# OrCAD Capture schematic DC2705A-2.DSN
size B
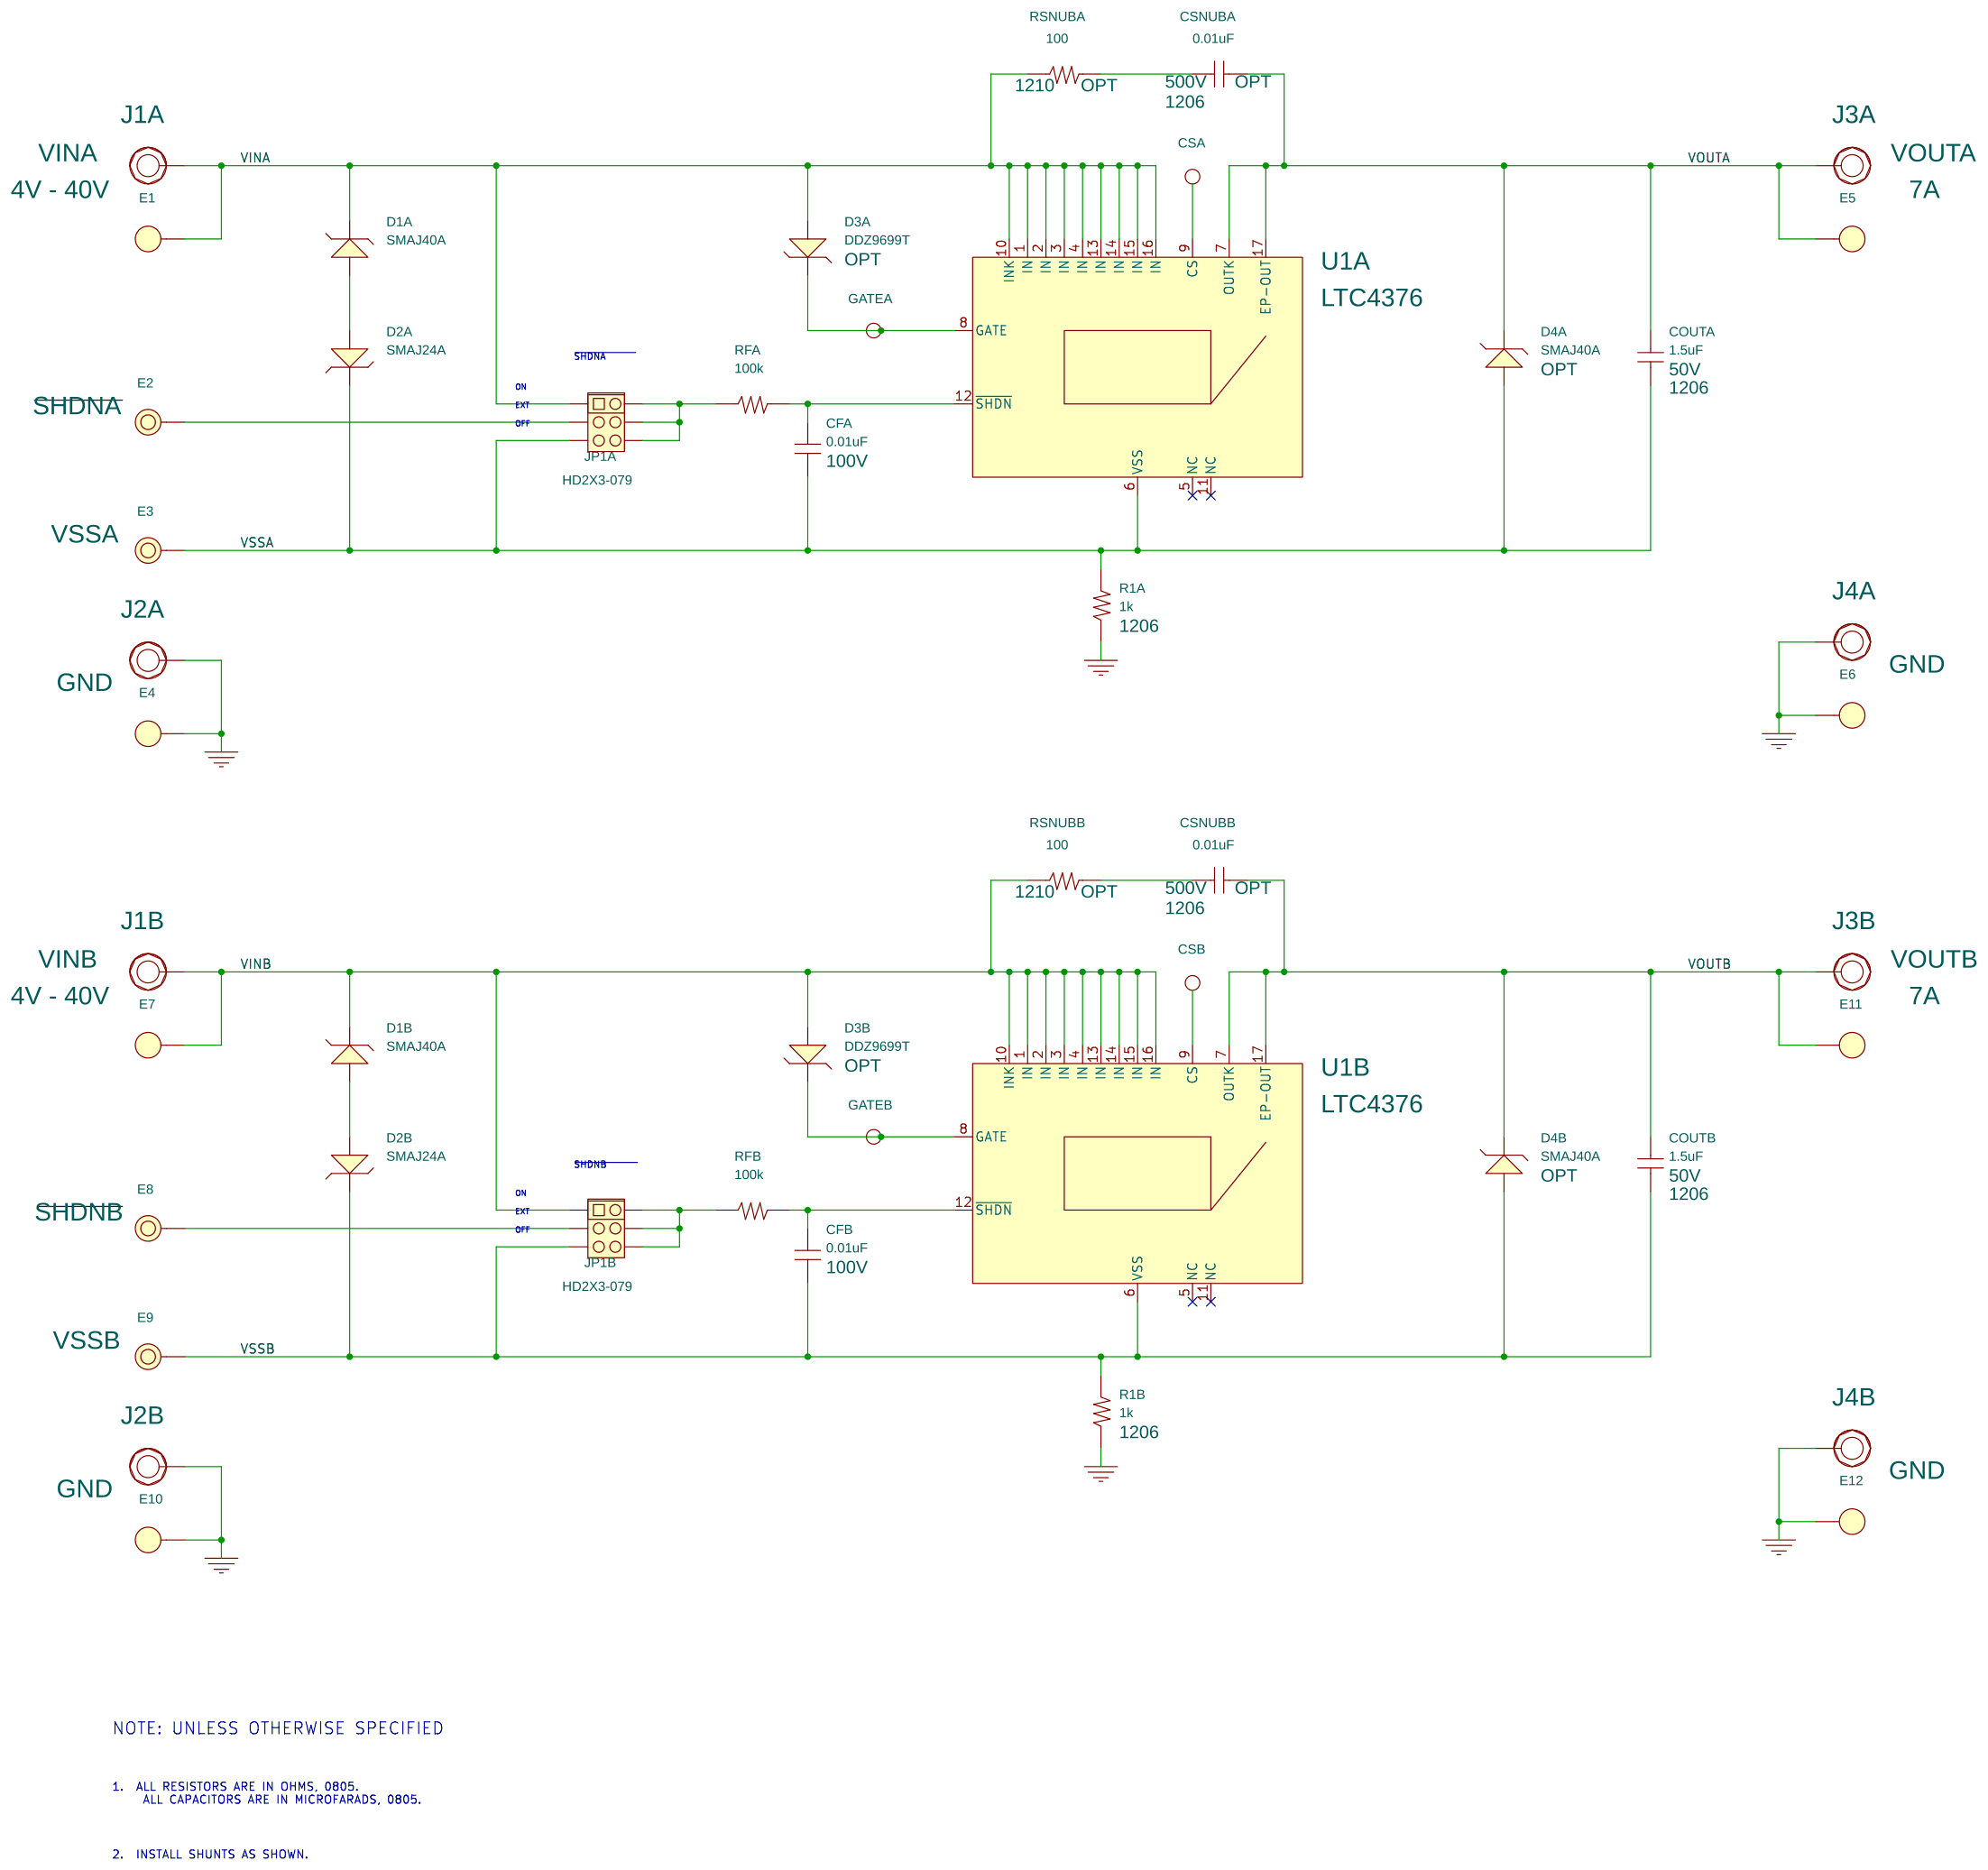
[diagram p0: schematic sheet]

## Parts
CFA  0.01uF  [0805]
CFB  0.01uF  [0805]
COUTA  1.5uF  [1206]
COUTB  1.5uF  [1206]
CSA  PAD100SMT  [PAD100SMT]
CSB  PAD100SMT  [PAD100SMT]
CSNUBA  0.01uF  [1206]
CSNUBB  0.01uF  [1206]
D1A  SMAJ40A  [SMA-DIODE]
D1B  SMAJ40A  [SMA-DIODE]
D2A  SMAJ24A  [SMA-DIODE]
D2B  SMAJ24A  [SMA-DIODE]
D3A  DDZ9699T  [SOD523]
D3B  DDZ9699T  [SOD523]
D4A  SMAJ40A  [SMA-DIODE]
D4B  SMAJ40A  [SMA-DIODE]
E1  MIL-MAX-2501  [MILL-MAX-2501]
E2  MIL-MAX-2308  [MILL-MAX-2308]
E3  MIL-MAX-2308  [MILL-MAX-2308]
E4  MIL-MAX-2501  [MILL-MAX-2501]
E5  MIL-MAX-2501  [MILL-MAX-2501]
E6  MIL-MAX-2501  [MILL-MAX-2501]
E7  MIL-MAX-2501  [MILL-MAX-2501]
E8  MIL-MAX-2308  [MILL-MAX-2308]
E9  MIL-MAX-2308  [MILL-MAX-2308]
E10  MIL-MAX-2501  [MILL-MAX-2501]
E11  MIL-MAX-2501  [MILL-MAX-2501]
E12  MIL-MAX-2501  [MILL-MAX-2501]
GATEA  PAD100SMT  [PAD100SMT]
GATEB  PAD100SMT  [PAD100SMT]
J1A  Banana Jack  [KEY-575]
J1B  Banana Jack  [KEY-575]
J2A  Banana Jack  [KEY-575]
J2B  Banana Jack  [KEY-575]
J3A  Banana Jack  [KEY-575]
J3B  Banana Jack  [KEY-575]
J4A  Banana Jack  [KEY-575]
J4B  Banana Jack  [KEY-575]
JP1A  HD2X3-079  [HD2X3-079]
JP1B  HD2X3-079  [HD2X3-079]
R1A  1k  [1206]
R1B  1k  [1206]
RFA  100k  [0805]
RFB  100k  [0805]
RSNUBA  100  [1210]
RSNUBB  100  [1210]
U1A  LTC4376  [DFN16DHD-5X4]
U1B  LTC4376  [DFN16DHD-5X4]

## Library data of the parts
CFA CFB = CAP-NP: VOLTAGE: 100V
COUTA COUTB = CAP-NP: VOLTAGE: 50V
CSA CSB GATEA GATEB = E-100-25
CSNUBA CSNUBB = CAP-NP: OPT: OPT; VOLTAGE: 500V
D1A D1B D2A D2B = SMAJ40A-SMA-DIODE
D3A D3B = DIODE-DDZ9699T-SOD523: OPT: OPT
D4A D4B = SMAJ40A-SMA-DIODE: OPT: OPT
E1 E4-E7 E10-E12 = E-094
E2 = E-064: 1ST PART FIELD: SHDNA
E3 = E-064: 1ST PART FIELD: VSSA
E8 = E-064: 1ST PART FIELD: SHDNB
E9 = E-064: 1ST PART FIELD: VSSB
J1A = E-KEY-575: 1ST PART FIELD: 4V - 40V; FUNTION: VINA
J1B = E-KEY-575: 1ST PART FIELD: 4V - 40V; FUNTION: VINB
J2A J2B J4A J4B = E-KEY-575: FUNTION: GND
J3A = E-KEY-575: 1ST PART FIELD: 7A; FUNTION: VOUTA
J3B = E-KEY-575: 1ST PART FIELD: 7A; FUNTION: VOUTB
JP1A JP1B = HD2X3-079_0
R1A R1B RFA RFB = R
RSNUBA RSNUBB = R: OPT: OPT
U1A U1B = LTC4376IDHD-DFN16DHD-5X4

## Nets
GND: E4.1(A) E6.1(A) E10.1(A) E12.1(A) J2A.1 J2B.1 J4A.1 J4B.1 R1A.1 R1B.1
VINA: D1A.1 D3A.2 E1.1(A) J1A.1 JP1A.1 RSNUBA.1 U1A.1(IN) U1A.2(IN) U1A.3(IN) U1A.4(IN) U1A.10(INK) U1A.13(IN) U1A.14(IN) U1A.15(IN) U1A.16(IN)
VINB: D1B.1 D3B.2 E7.1(A) J1B.1 JP1B.1 RSNUBB.1 U1B.1(IN) U1B.2(IN) U1B.3(IN) U1B.4(IN) U1B.10(INK) U1B.13(IN) U1B.14(IN) U1B.15(IN) U1B.16(IN)
VSSA: CFA.2 COUTA.2 D2A.1 D4A.2 E3.1(A) JP1A.5 R1A.2 U1A.6(VSS)
VSSB: CFB.2 COUTB.2 D2B.1 D4B.2 E9.1(A) JP1B.5 R1B.2 U1B.6(VSS)
VOUTA: COUTA.1 CSNUBA.2 D4A.1 E5.1(A) J3A.1 U1A.7(OUTK) U1A.17(EP-OUT)
VOUTB: COUTB.1 CSNUBB.2 D4B.1 E11.1(A) J3B.1 U1B.7(OUTK) U1B.17(EP-OUT)
N00685: D3A.1 GATEA.1 U1A.8(GATE)
N00951: CFA.1 RFA.2 U1A.12(~{SHDN})
N01382: CSA.1 U1A.9(CS)
N02836: CSNUBA.1 RSNUBA.2
N04073: JP1A.2 JP1A.4 JP1A.6 RFA.1
N04138: E2.1(A) JP1A.3
N05364: D1A.2 D2A.2
N09423: D3B.1 GATEB.1 U1B.8(GATE)
N09453: CFB.1 RFB.2 U1B.12(~{SHDN})
N09569: CSB.1 U1B.9(CS)
N09739: CSNUBB.1 RSNUBB.2
N09887: JP1B.2 JP1B.4 JP1B.6 RFB.1
N09911: E8.1(A) JP1B.3
N10061: D1B.2 D2B.2

Not connected (* = marked no-connect by the designer): U1A 5(NC)* 11(NC)*; U1B 5(NC)* 11(NC)*

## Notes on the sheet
- SHDNA
- ON
- EXT
- OFF
- SHDNB
- ON
- EXT
- OFF
- NOTE: UNLESS OTHERWISE SPECIFIED
- 1.  ALL RESISTORS ARE IN OHMS, 0805.
       ALL CAPACITORS ARE IN MICROFARADS, 0805.
- 2.  INSTALL SHUNTS AS SHOWN.
